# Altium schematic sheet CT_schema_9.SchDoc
size 274 x 160 mm
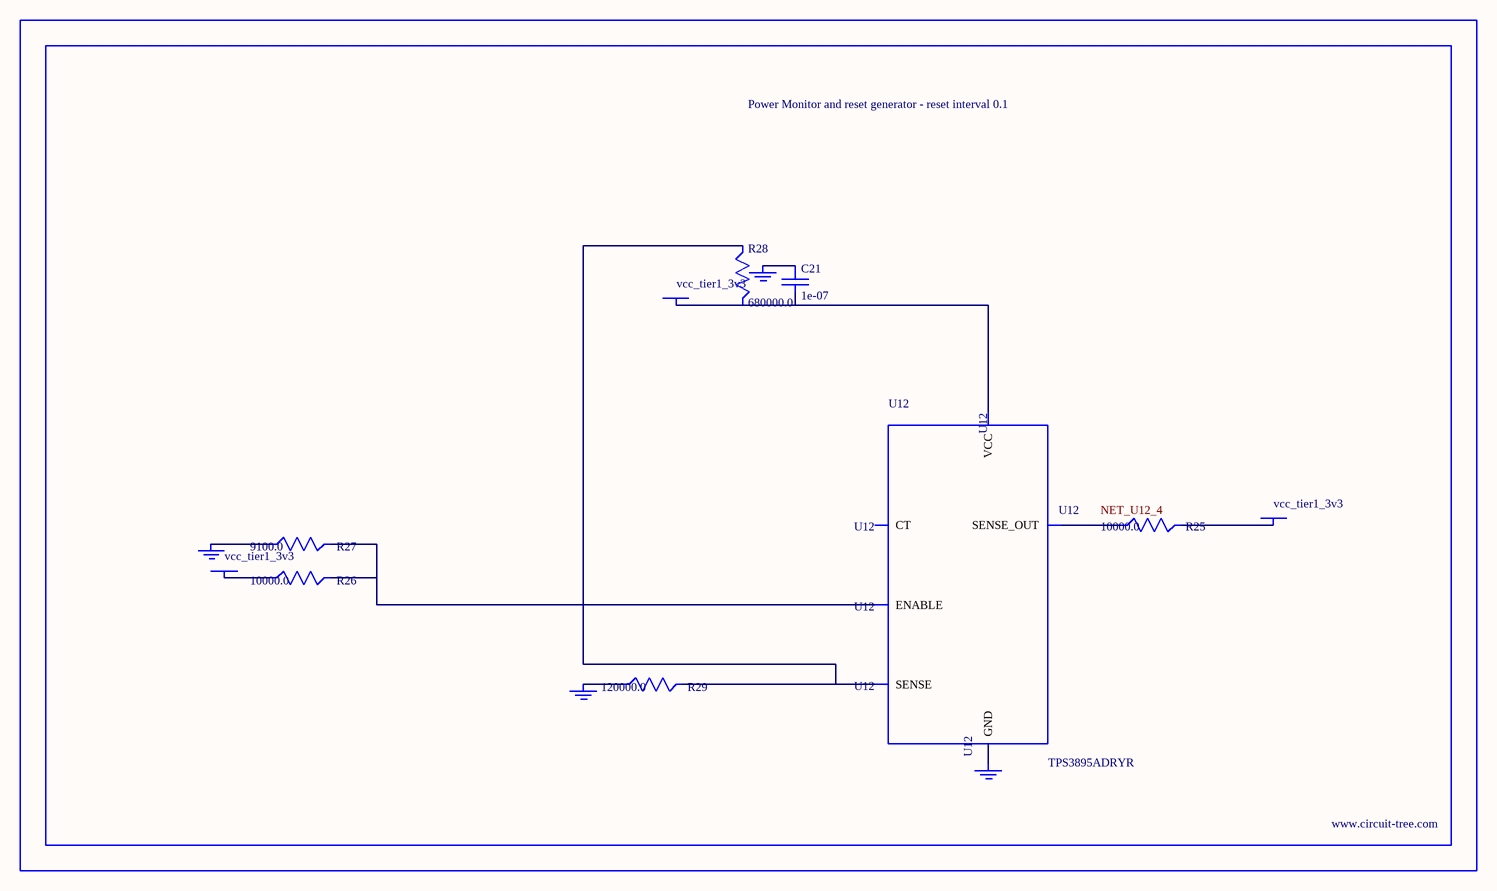
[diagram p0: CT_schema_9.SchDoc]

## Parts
BORDER8  (no value)
C21  1e-07  [C0402]
GND_INSTANCE_8_0  (no value)
GND_INSTANCE_8_1  (no value)
GND_INSTANCE_8_2  (no value)
GND_INSTANCE_8_3  (no value)
POWER_INSTANCE_8_0  vcc_tier1_3v3
POWER_INSTANCE_8_1  vcc_tier1_3v3
POWER_INSTANCE_8_2  vcc_tier1_3v3
R25  10000.0  [R0603]
R26  10000.0  [R0603]
R27  9100.0  [R0603]
R28  680000.0  [R0603]
R29  120000.0  [R0603]
U12  TPS3895ADRYR  [SON-6]

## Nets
NetC21_1: C21.1 GND_INSTANCE_8_2.0(GND)
NetC21_2: C21.2 POWER_INSTANCE_8_2.0(PWR) R28.2 U12.6(VCC)
NetGND_INSTANCE_8_0_0: GND_INSTANCE_8_0.0(GND) R27.1
NetGND_INSTANCE_8_1_0: GND_INSTANCE_8_1.0(GND) R29.1
NetGND_INSTANCE_8_3_0: GND_INSTANCE_8_3.0(GND) U12.2(GND)
NetPOWER_INSTANCE_8_0_0: POWER_INSTANCE_8_0.0(PWR) R26.1
NetPOWER_INSTANCE_8_1_0: POWER_INSTANCE_8_1.0(PWR) R25.2
NetR25_1: R25.1 U12.4(SENSE_OUT)
NetR26_2: R26.2 R27.2 U12.1(ENABLE)
NetR28_1: R28.1 R29.2 U12.3(SENSE)

Not connected (* = marked no-connect by the designer): U12 5(CT)

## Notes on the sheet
- Labels drawn without touching a wire or pin: NET_U12_4

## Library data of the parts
BORDER8 = BORDER_PAGE8
C21 = C0402C104K3RACTU
GND_INSTANCE_8_0-GND_INSTANCE_8_3 = GND
POWER_INSTANCE_8_0-POWER_INSTANCE_8_2 = PWR
R25 R26 = RC0603JR-0710KL
R27 = RC0603JR-079K1L
R28 = RC0603JR-07680KL
R29 = RC0603JR-07120KL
